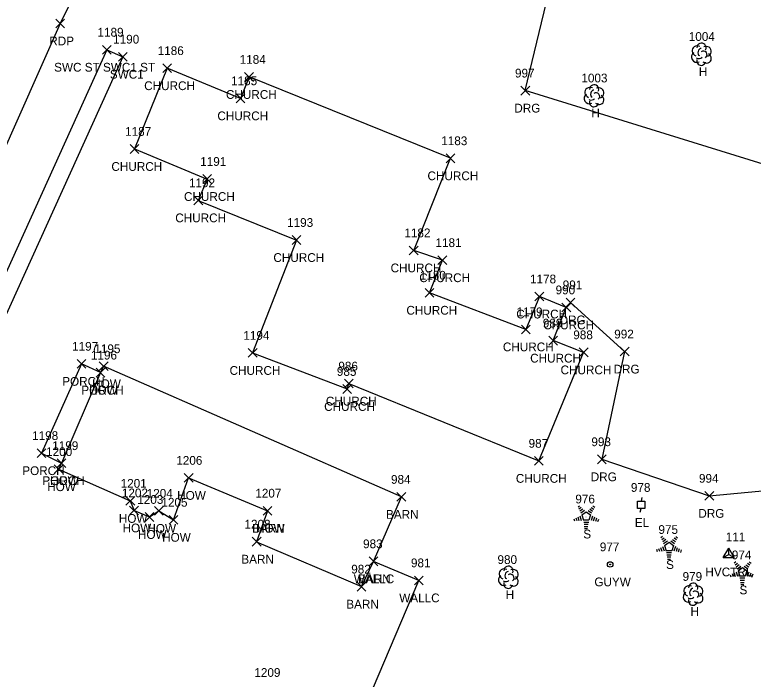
# Model space of a CAD drawing. Extents: x 1767353 to 1772625, y 740790 to 747702.
# Drawn here: x 1770077.3 to 1770245.8, y 742414.3 to 742566 of the extents above; entities that cross this region are included whole.
import ezdxf

# ---------------------------------------------------------------- set-up
doc = ezdxf.new("R2010")
doc.units = 0
for name, color, linetype in [('C_A', 7, 'Continuous'), ('C_I', 7, 'Continuous'), ('CPSM', 7, 'Continuous'), ('L_A', 7, 'Continuous'), ('L_I', 7, 'Continuous'), ('L_TIC', 7, 'Continuous'), ('LBC', 7, 'Continuous'), ('LBF', 7, 'Continuous'), ('LTC', 7, 'Continuous'), ('LTD', 7, 'Continuous'), ('LW', 7, 'Continuous'), ('P_A', 7, 'Continuous'), ('P_TIC', 7, 'Continuous'), ('PET', 7, 'Continuous'), ('R_A', 7, 'Continuous'), ('R_I', 7, 'Continuous'), ('R_TIC', 7, 'Continuous'), ('RDG', 7, 'Continuous'), ('RSW', 7, 'Continuous'), ('U_A', 7, 'Continuous'), ('U_I', 7, 'Continuous'), ('UEPT', 7, 'Continuous'), ('UPGW', 7, 'Continuous')]:
    doc.layers.add(name, color=color, linetype=linetype)

msp = doc.modelspace()

# ---------------------------------------------------------------- linework, layer by layer
at = {"layer": 'CPSM'}
for p, q in [((1770238.94, 742442.11), (1770240.19, 742444.27)), ((1770238.94, 742442.11), (1770240.19, 742442.83)), ((1770241.44, 742442.11), (1770240.19, 742444.27)), ((1770240.19, 742442.83), (1770240.19, 742444.27)), ((1770240.19, 742442.83), (1770240.19, 742442.83)), ((1770240.19, 742442.83), (1770241.44, 742442.11)), ((1770238.94, 742442.11), (1770241.44, 742442.11))]:
    msp.add_line(p, q, dxfattribs=at)
at = {"layer": 'L_TIC'}
for points in [[(1770111.12, 742552.84), (1770113.12, 742554.84)], [(1770113.12, 742552.84), (1770111.12, 742554.84)], [(1770129.77, 742550.84), (1770131.77, 742552.84)], [(1770131.77, 742550.84), (1770129.77, 742552.84)], [(1770127.81, 742545.96), (1770129.81, 742547.96)], [(1770129.81, 742545.96), (1770127.81, 742547.96)], [(1770103.64, 742534.4), (1770105.64, 742536.4)], [(1770105.64, 742534.4), (1770103.64, 742536.4)], [(1770175.74, 742532.27), (1770177.74, 742534.27)], [(1770177.74, 742532.27), (1770175.74, 742534.27)], [(1770120.2, 742527.54), (1770122.2, 742529.54)], [(1770122.2, 742527.54), (1770120.2, 742529.54)], [(1770118.21, 742522.67), (1770120.21, 742524.67)], [(1770120.21, 742522.67), (1770118.21, 742524.67)], [(1770140.59, 742513.61), (1770142.59, 742515.61)], [(1770142.59, 742513.61), (1770140.59, 742515.61)], [(1770167.33, 742511.24), (1770169.33, 742513.24)], [(1770169.33, 742511.24), (1770167.33, 742513.24)], [(1770173.87, 742509), (1770175.87, 742511)], [(1770175.87, 742509), (1770173.87, 742511)], [(1770170.93, 742501.57), (1770172.93, 742503.57)], [(1770172.93, 742501.57), (1770170.93, 742503.57)], [(1770196, 742500.71), (1770198, 742502.71)], [(1770198, 742500.71), (1770196, 742502.71)], [(1770202.15, 742498.22), (1770204.15, 742500.22)], [(1770204.15, 742498.22), (1770202.15, 742500.22)], [(1770192.94, 742493.21), (1770194.94, 742495.21)], [(1770194.94, 742493.21), (1770192.94, 742495.21)], [(1770199.16, 742490.64), (1770201.16, 742492.64)], [(1770201.16, 742490.64), (1770199.16, 742492.64)], [(1770206.1, 742487.96), (1770208.1, 742489.96)], [(1770208.1, 742487.96), (1770206.1, 742489.96)], [(1770130.6, 742487.83), (1770132.6, 742489.83)], [(1770132.6, 742487.83), (1770130.6, 742489.83)], [(1770091.54, 742485.34), (1770093.54, 742487.34)], [(1770093.54, 742485.34), (1770091.54, 742487.34)], [(1770096.61, 742484.79), (1770098.61, 742486.79)], [(1770098.61, 742484.79), (1770096.61, 742486.79)], [(1770095.89, 742483.33), (1770097.89, 742485.33)], [(1770097.89, 742483.33), (1770095.89, 742485.33)], [(1770095.89, 742483.33), (1770097.89, 742485.33)], [(1770097.89, 742483.33), (1770095.89, 742485.33)], [(1770152.17, 742479.6), (1770154.17, 742481.6)], [(1770154.17, 742479.6), (1770152.17, 742481.6)], [(1770152.56, 742480.83), (1770154.56, 742482.83)], [(1770154.56, 742480.83), (1770152.56, 742482.83)], [(1770082.43, 742464.95), (1770084.43, 742466.95)], [(1770084.43, 742464.95), (1770082.43, 742466.95)], [(1770195.9, 742463.19), (1770197.9, 742465.19)], [(1770197.9, 742463.19), (1770195.9, 742465.19)], [(1770086.35, 742461.29), (1770088.35, 742463.29)], [(1770088.35, 742461.29), (1770086.35, 742463.29)], [(1770087.02, 742462.66), (1770089.02, 742464.66)], [(1770089.02, 742462.66), (1770087.02, 742464.66)], [(1770087.02, 742462.66), (1770089.02, 742464.66)], [(1770089.02, 742462.66), (1770087.02, 742464.66)], [(1770116, 742459.3), (1770118, 742461.3)], [(1770118, 742459.3), (1770116, 742461.3)], [(1770164.52, 742454.96), (1770166.52, 742456.96)], [(1770166.52, 742454.96), (1770164.52, 742456.96)], [(1770102.69, 742454.05), (1770104.69, 742456.05)], [(1770104.69, 742454.05), (1770102.69, 742456.05)], [(1770103.54, 742451.87), (1770105.54, 742453.87)], [(1770105.54, 742451.87), (1770103.54, 742453.87)], [(1770109.21, 742451.77), (1770111.21, 742453.77)], [(1770111.21, 742451.77), (1770109.21, 742453.77)], [(1770133.98, 742451.81), (1770135.98, 742453.81)], [(1770135.98, 742451.81), (1770133.98, 742453.81)], [(1770133.98, 742451.81), (1770135.98, 742453.81)], [(1770135.98, 742451.81), (1770133.98, 742453.81)], [(1770107.05, 742450.38), (1770109.05, 742452.38)], [(1770109.05, 742450.38), (1770107.05, 742452.38)], [(1770112.57, 742449.73), (1770114.57, 742451.73)], [(1770114.57, 742449.73), (1770112.57, 742451.73)], [(1770131.51, 742444.74), (1770133.51, 742446.74)], [(1770133.51, 742444.74), (1770131.51, 742446.74)], [(1770158.15, 742440.25), (1770160.15, 742442.25)], [(1770160.15, 742440.25), (1770158.15, 742442.25)], [(1770158.15, 742440.25), (1770160.15, 742442.25)], [(1770160.15, 742440.25), (1770158.15, 742442.25)], [(1770168.51, 742435.9), (1770170.51, 742437.9)], [(1770170.51, 742435.9), (1770168.51, 742437.9)], [(1770155.45, 742434.47), (1770157.45, 742436.47)], [(1770157.45, 742434.47), (1770155.45, 742436.47)]]:
    msp.add_lwpolyline(points, dxfattribs=at)
at = {"layer": 'LBC'}
for points in [[(1770153.17, 742480.6), (1770153.56, 742481.83), (1770196.9, 742464.19), (1770207.1, 742488.96), (1770200.16, 742491.64), (1770203.15, 742499.22), (1770197, 742501.71), (1770193.94, 742494.21), (1770171.93, 742502.57), (1770174.87, 742510), (1770168.33, 742512.24), (1770176.74, 742533.27), (1770130.77, 742551.84), (1770128.81, 742546.96), (1770112.12, 742553.84), (1770104.64, 742535.4), (1770121.2, 742528.54), (1770119.21, 742523.67), (1770141.59, 742514.61), (1770131.6, 742488.83)], [(1770131.6, 742488.83), (1770153.17, 742480.6)], [(1770097.61, 742485.79), (1770096.89, 742484.33), (1770088.02, 742463.66), (1770087.35, 742462.29), (1770103.69, 742455.05), (1770104.54, 742452.87), (1770108.05, 742451.38), (1770110.21, 742452.77), (1770113.57, 742450.73), (1770117, 742460.3), (1770134.98, 742452.81)], [(1770165.52, 742455.96), (1770097.61, 742485.79)], [(1770156.45, 742435.47), (1770159.15, 742441.25), (1770165.52, 742455.96)], [(1770134.98, 742452.81), (1770132.51, 742445.74)], [(1770132.51, 742445.74), (1770156.45, 742435.47)]]:
    msp.add_lwpolyline(points, dxfattribs=at)
at = {"layer": 'LBF'}
msp.add_lwpolyline([(1770096.89, 742484.33), (1770092.54, 742486.34), (1770083.43, 742465.95), (1770088.02, 742463.66)], dxfattribs=at)
at = {"layer": 'LTC'}
for p, q in [((1770205.82, 742453.69), (1770206.18, 742453.95)), ((1770206.03, 742453.23), (1770206.56, 742453.61)), ((1770206.24, 742452.76), (1770206.95, 742453.27)), ((1770206.45, 742452.29), (1770207.33, 742452.93)), ((1770208.48, 742453.23), (1770209.16, 742452.74)), ((1770208.85, 742453.58), (1770209.4, 742453.18)), ((1770209.22, 742453.93), (1770209.64, 742453.63)), ((1770205.77, 742451.4), (1770206.04, 742450.57)), ((1770206.22, 742451.62), (1770206.55, 742450.6)), ((1770206.68, 742451.84), (1770207.69, 742452.57)), ((1770206.68, 742451.84), (1770207.07, 742450.65)), ((1770207.69, 742452.57), (1770208.69, 742451.85)), ((1770208.11, 742452.89), (1770208.92, 742452.3)), ((1770208.69, 742451.85), (1770208.3, 742450.65)), ((1770209.12, 742451.58), (1770208.79, 742450.54)), ((1770209.57, 742451.33), (1770209.28, 742450.44)), ((1770204.86, 742450.97), (1770205.01, 742450.5)), ((1770205.31, 742451.19), (1770205.52, 742450.54)), ((1770208.3, 742450.65), (1770207.07, 742450.65)), ((1770208.26, 742450.15), (1770207.11, 742450.15)), ((1770208.17, 742449.65), (1770207.19, 742449.65)), ((1770210.01, 742451.08), (1770209.78, 742450.35)), ((1770210.46, 742450.83), (1770210.27, 742450.25)), ((1770208.09, 742449.15), (1770207.26, 742449.15)), ((1770208.01, 742448.65), (1770207.33, 742448.65)), ((1770224.72, 742446.72), (1770225.07, 742446.98)), ((1770224.93, 742446.25), (1770225.46, 742446.64)), ((1770225.14, 742445.79), (1770225.84, 742446.3)), ((1770227.38, 742446.26), (1770228.05, 742445.77)), ((1770227.75, 742446.61), (1770228.3, 742446.21)), ((1770228.12, 742446.96), (1770228.54, 742446.65)), ((1770225.12, 742444.65), (1770225.45, 742443.63)), ((1770225.35, 742445.32), (1770226.23, 742445.96)), ((1770225.57, 742444.87), (1770226.58, 742445.6)), ((1770225.57, 742444.87), (1770225.96, 742443.67)), ((1770226.58, 742445.6), (1770227.58, 742444.88)), ((1770227, 742445.91), (1770227.81, 742445.33)), ((1770227.58, 742444.88), (1770227.19, 742443.67)), ((1770228.02, 742444.61), (1770227.68, 742443.57)), ((1770223.75, 742444), (1770223.9, 742443.53)), ((1770224.21, 742444.21), (1770224.42, 742443.56)), ((1770224.66, 742444.43), (1770224.93, 742443.6)), ((1770227.19, 742443.67), (1770225.96, 742443.67)), ((1770227.15, 742443.17), (1770226.01, 742443.17)), ((1770228.46, 742444.35), (1770228.18, 742443.47)), ((1770228.91, 742444.1), (1770228.67, 742443.38)), ((1770229.35, 742443.85), (1770229.17, 742443.28)), ((1770227.07, 742442.67), (1770226.08, 742442.67)), ((1770226.98, 742442.17), (1770226.15, 742442.17)), ((1770226.9, 742441.67), (1770226.23, 742441.67)), ((1770241.47, 742440.92), (1770241.82, 742441.18)), ((1770244.87, 742441.17), (1770245.29, 742440.86)), ((1770241.68, 742440.46), (1770242.21, 742440.84)), ((1770241.89, 742439.99), (1770242.59, 742440.5)), ((1770242.1, 742439.53), (1770242.98, 742440.17)), ((1770242.32, 742439.07), (1770243.33, 742439.81)), ((1770243.33, 742439.81), (1770244.33, 742439.08)), ((1770243.75, 742440.12), (1770244.56, 742439.53)), ((1770244.13, 742440.47), (1770244.8, 742439.97)), ((1770244.5, 742440.82), (1770245.05, 742440.42)), ((1770240.5, 742438.2), (1770240.65, 742437.74)), ((1770240.96, 742438.42), (1770241.17, 742437.77)), ((1770241.41, 742438.64), (1770241.68, 742437.8)), ((1770241.87, 742438.85), (1770242.2, 742437.83)), ((1770242.32, 742439.07), (1770242.71, 742437.88)), ((1770243.94, 742437.88), (1770242.71, 742437.88)), ((1770244.33, 742439.08), (1770243.94, 742437.88)), ((1770244.77, 742438.81), (1770244.43, 742437.77)), ((1770245.21, 742438.56), (1770244.93, 742437.68)), ((1770245.66, 742438.31), (1770245.42, 742437.58)), ((1770243.9, 742437.38), (1770242.76, 742437.38)), ((1770243.82, 742436.88), (1770242.83, 742436.88)), ((1770243.73, 742436.38), (1770242.9, 742436.38)), ((1770243.65, 742435.88), (1770242.98, 742435.88))]:
    msp.add_line(p, q, dxfattribs=at)
at = {"layer": 'LTD'}
for p, q in [((1770233.93, 742557.07), (1770233.93, 742557.07)), ((1770233.93, 742557.07), (1770233.93, 742557.07)), ((1770209.44, 742547.6), (1770209.44, 742547.6)), ((1770209.44, 742547.6), (1770209.44, 742547.6)), ((1770189.9, 742437.65), (1770189.9, 742437.65)), ((1770189.9, 742437.65), (1770189.9, 742437.65)), ((1770232.04, 742433.8), (1770232.04, 742433.8)), ((1770232.04, 742433.8), (1770232.04, 742433.8))]:
    msp.add_line(p, q, dxfattribs=at)
for centre in [(1770233.98, 742558.5), (1770209.49, 742549.03), (1770189.95, 742439.09), (1770232.09, 742435.24)]:
    msp.add_arc(centre, 1.05, 335.5272, 180.9563, dxfattribs=at)
for centre, major_axis, ratio, start_param, end_param in [((1770233.14, 742557.73), (1.21, -0.51), 0.895232, 1.570796, 4.712389), ((1770232.85, 742556.36), (0.58, -1.04), 0.959034, 3.141593, 6.283185), ((1770233.72, 742557.53), (-0.208, -0.792), 0.645439, 3.141593, 6.283185), ((1770234.43, 742556.9), (-0.5, 0.667), 0.989748, 3.141593, 6.283185), ((1770234.97, 742557.65), (-1.14, -0.48), 0.949671, 1.570796, 4.712389), ((1770233.93, 742555.57), (0.26, 1.06), 0.942809, 1.570796, 4.712389), ((1770233.48, 742556.32), (-0.625, -0.083), 0.423636, 0, 3.141593), ((1770234.93, 742556.23), (-1.09, 0.79), 0.841452, 1.570796, 4.712389), ((1770208.65, 742548.26), (1.21, -0.51), 0.895232, 1.570796, 4.712389), ((1770209.23, 742548.05), (-0.208, -0.792), 0.645439, 3.141593, 6.283185), ((1770210.48, 742548.18), (-1.14, -0.48), 0.949671, 1.570796, 4.712389), ((1770208.36, 742546.89), (0.58, -1.04), 0.959034, 3.141593, 6.283185), ((1770209.94, 742547.43), (-0.5, 0.667), 0.989748, 3.141593, 6.283185), ((1770210.44, 742546.76), (-1.09, 0.79), 0.841452, 1.570796, 4.712389), ((1770209.44, 742546.1), (0.26, 1.06), 0.942809, 1.570796, 4.712389), ((1770208.98, 742546.85), (-0.625, -0.083), 0.423636, 0, 3.141593), ((1770189.11, 742438.32), (1.21, -0.51), 0.895232, 1.570796, 4.712389), ((1770190.94, 742438.24), (-1.14, -0.48), 0.949671, 1.570796, 4.712389), ((1770188.82, 742436.94), (0.58, -1.04), 0.959034, 3.141593, 6.283185), ((1770189.69, 742438.11), (-0.208, -0.792), 0.645439, 3.141593, 6.283185), ((1770190.4, 742437.49), (-0.5, 0.667), 0.989748, 3.141593, 6.283185), ((1770189.9, 742436.15), (0.26, 1.06), 0.942809, 1.570796, 4.712389), ((1770189.44, 742436.9), (-0.625, -0.083), 0.423636, 0, 3.141593), ((1770190.9, 742436.82), (-1.09, 0.79), 0.841452, 1.570796, 4.712389), ((1770231.25, 742434.47), (1.21, -0.51), 0.895232, 1.570796, 4.712389), ((1770231.83, 742434.26), (-0.208, -0.792), 0.645439, 3.141593, 6.283185), ((1770232.54, 742433.64), (-0.5, 0.667), 0.989748, 3.141593, 6.283185), ((1770233.08, 742434.39), (-1.14, -0.48), 0.949671, 1.570796, 4.712389), ((1770230.96, 742433.1), (0.58, -1.04), 0.959034, 3.141593, 6.283185), ((1770231.58, 742433.05), (-0.625, -0.083), 0.423636, 0, 3.141593), ((1770233.04, 742432.97), (-1.09, 0.79), 0.841452, 1.570796, 4.712389), ((1770232.04, 742432.3), (0.26, 1.06), 0.942809, 1.570796, 4.712389)]:
    msp.add_ellipse(centre, major_axis=major_axis, ratio=ratio, start_param=start_param, end_param=end_param, dxfattribs=at)
at = {"layer": 'LW'}
msp.add_lwpolyline([(1770155.04, 742402.89), (1770169.51, 742436.9), (1770159.15, 742441.25)], dxfattribs=at)
at = {"layer": 'P_TIC'}
for points in [[(1770086.72, 742563.06), (1770088.72, 742565.06)], [(1770088.72, 742563.06), (1770086.72, 742565.06)]]:
    msp.add_lwpolyline(points, dxfattribs=at)
at = {"layer": 'PET'}
msp.add_lwpolyline([(1770147.48, 742699.94), (1770126.77, 742647.43), (1770093.35, 742575.6), (1770087.72, 742564.06), (1770014.02, 742398.02), (1769942.32, 742243.2), (1769914.15, 742124.85), (1769908.32, 742119.68), (1769902.88, 742101.36), (1769903.35, 742099.19), (1769904.66, 742097.46), (1769909.68, 742095.79), (1770083.39, 742045.68), (1770106.4, 742043.42), (1770086.96, 742009.25), (1770086.23, 742007.27), (1770086.55, 742005.47), (1770087.9, 742003.62), (1770089.26, 742002.56), (1770097.29, 741998.16), (1770140.08, 741981.73)], dxfattribs=at)
at = {"layer": 'R_TIC'}
for points in [[(1770097.34, 742557.06), (1770099.34, 742559.06)], [(1770099.34, 742557.06), (1770097.34, 742559.06)], [(1770097.34, 742557.06), (1770099.34, 742559.06)], [(1770099.34, 742557.06), (1770097.34, 742559.06)], [(1770100.99, 742555.46), (1770102.99, 742557.46)], [(1770102.99, 742555.46), (1770100.99, 742557.46)], [(1770192.8, 742547.72), (1770194.8, 742549.72)], [(1770194.8, 742547.72), (1770192.8, 742549.72)], [(1770203.13, 742499.37), (1770205.13, 742501.37)], [(1770205.13, 742499.37), (1770203.13, 742501.37)], [(1770215.45, 742488.14), (1770217.45, 742490.14)], [(1770217.45, 742488.14), (1770215.45, 742490.14)], [(1770210.23, 742463.55), (1770212.23, 742465.55)], [(1770212.23, 742463.55), (1770210.23, 742465.55)], [(1770234.77, 742455.2), (1770236.77, 742457.2)], [(1770236.77, 742455.2), (1770234.77, 742457.2)]]:
    msp.add_lwpolyline(points, dxfattribs=at)
at = {"layer": 'RDG'}
msp.add_lwpolyline([(1770204.13, 742500.37), (1770216.45, 742489.14), (1770211.23, 742464.55), (1770235.77, 742456.2), (1770257.57, 742458.3), (1770267.19, 742526.02), (1770193.8, 742548.72), (1770201.83, 742582.22)], dxfattribs=at)
at = {"layer": 'RSW'}
for points in [[(1770098.34, 742558.06), (1770024.1, 742393.92), (1769953.58, 742237.06), (1769937.36, 742200.11), (1769932.58, 742188.49)], [(1770098.34, 742558.06), (1770101.99, 742556.46), (1770027.61, 742392.19), (1769957.88, 742235.71), (1769937.16, 742186.55), (1769936.48, 742178.62)]]:
    msp.add_lwpolyline(points, dxfattribs=at)
at = {"layer": 'UEPT'}
for p, q in [((1770219.41, 742453.29), (1770219.41, 742454.96)), ((1770219.41, 742454.96), (1770221.07, 742454.96)), ((1770220.41, 742455.79), (1770220.24, 742454.96)), ((1770221.07, 742454.96), (1770221.07, 742453.29)), ((1770221.07, 742453.29), (1770219.41, 742453.29)), ((1770219.99, 742452.46), (1770220.24, 742453.29)), ((1770220.24, 742454.12), (1770220.24, 742454.12))]:
    msp.add_line(p, q, dxfattribs=at)
at = {"layer": 'UPGW'}
for radius in [0.625, 0.0833]:
    msp.add_circle((1770213.15, 742440.55), radius, dxfattribs=at)

# ---------------------------------------------------------------- texts
at = {"layer": 'C_A'}
msp.add_text('HVCTRL', height=2, dxfattribs=at).set_placement((1770234.88, 742437.83))
at = {"layer": 'C_I'}
msp.add_text('111', height=2, dxfattribs=at).set_placement((1770239.52, 742445.83))
at = {"layer": 'L_A'}
for s, p in [('H', (1770233.37, 742552.07)), ('CHURCH', (1770106.86, 742548.84)), ('CHURCH', (1770125.51, 742546.84)), ('CHURCH', (1770123.55, 742541.96)), ('H', (1770208.87, 742542.6)), ('CHURCH', (1770099.38, 742530.4)), ('CHURCH', (1770171.48, 742528.27)), ('CHURCH', (1770115.94, 742523.54)), ('CHURCH', (1770113.95, 742518.67)), ('CHURCH', (1770136.33, 742509.61)), ('CHURCH', (1770163.07, 742507.24)), ('CHURCH', (1770169.61, 742505)), ('CHURCH', (1770166.67, 742497.57)), ('CHURCH', (1770191.74, 742496.71)), ('CHURCH', (1770197.89, 742494.22)), ('CHURCH', (1770188.68, 742489.21)), ('CHURCH', (1770194.9, 742486.64)), ('CHURCH', (1770126.34, 742483.83)), ('CHURCH', (1770201.84, 742483.96)), ('PORCH', (1770088.16, 742481.34)), ('HOW', (1770095, 742480.79)), ('PORCH', (1770092.52, 742479.33)), ('HOW', (1770094.28, 742479.33)), ('CHURCH', (1770148.3, 742476.83)), ('CHURCH', (1770147.91, 742475.6)), ('PORCH', (1770079.05, 742460.95)), ('PORCH', (1770083.64, 742458.66)), ('HOW', (1770085.4, 742458.66)), ('CHURCH', (1770191.64, 742459.19)), ('HOW', (1770084.74, 742457.29)), ('HOW', (1770114.39, 742455.3)), ('BARN', (1770162.03, 742450.96)), ('HOW', (1770101.08, 742450.05)), ('HOW', (1770101.93, 742447.87)), ('HOW', (1770107.59, 742447.77)), ('BARN', (1770131.49, 742447.81)), ('HOW', (1770132.37, 742447.81)), ('HOW', (1770105.44, 742446.38)), ('S', (1770207.02, 742446.48)), ('HOW', (1770110.95, 742445.73)), ('BARN', (1770129.02, 742440.74)), ('S', (1770225.91, 742439.51)), ('WALLC', (1770154.68, 742436.25)), ('BARN', (1770155.66, 742436.25)), ('H', (1770189.33, 742432.65)), ('S', (1770242.66, 742433.72)), ('WALLC', (1770165.04, 742431.9)), ('BARN', (1770152.96, 742430.47)), ('H', (1770231.47, 742428.8))]:
    msp.add_text(s, height=2, dxfattribs=at).set_placement(p)
at = {"layer": 'L_I'}
for s, p in [('1004', (1770231.08, 742560.07)), ('1186', (1770109.94, 742556.84)), ('1184', (1770128.64, 742554.84)), ('1003', (1770206.59, 742550.6)), ('1185', (1770126.68, 742549.96)), ('1187', (1770102.51, 742538.4)), ('1183', (1770174.62, 742536.27)), ('1191', (1770119.64, 742531.54)), ('1192', (1770117.08, 742526.67)), ('1193', (1770139.46, 742517.61)), ('1182', (1770166.21, 742515.24)), ('1181', (1770173.31, 742513)), ('1180', (1770169.72, 742505.57)), ('1178', (1770194.87, 742504.71)), ('990', (1770200.7, 742502.22)), ('1179', (1770191.8, 742497.21)), ('989', (1770197.79, 742494.64)), ('1194', (1770129.48, 742491.83)), ('988', (1770204.74, 742491.96)), ('1197', (1770090.41, 742489.34)), ('1195', (1770095.49, 742488.79)), ('1196', (1770094.71, 742487.33)), ('1196', (1770094.71, 742487.33)), ('986', (1770151.15, 742484.83)), ('985', (1770150.81, 742483.6)), ('1198', (1770081.3, 742468.95)), ('1199', (1770085.88, 742466.66)), ('1199', (1770085.88, 742466.66)), ('987', (1770194.54, 742467.19)), ('1200', (1770084.49, 742465.29)), ('1206', (1770114.18, 742463.3)), ('1201', (1770101.49, 742458.05)), ('984', (1770163.16, 742458.96)), ('1202', (1770101.77, 742455.87)), ('1203', (1770105.28, 742454.38)), ('1204', (1770107.43, 742455.77)), ('1207', (1770132.21, 742455.81)), ('1207', (1770132.21, 742455.81)), ('976', (1770205.21, 742454.48)), ('1205', (1770110.79, 742453.73)), ('1208', (1770129.74, 742448.74)), ('975', (1770224.16, 742447.51)), ('983', (1770156.79, 742444.25)), ('983', (1770156.79, 742444.25)), ('974', (1770240.91, 742441.72)), ('981', (1770167.71, 742439.9)), ('980', (1770187.45, 742440.65)), ('982', (1770154.09, 742438.47)), ('979', (1770229.67, 742436.8)), ('1209', (1770131.99, 742414.87))]:
    msp.add_text(s, height=2, dxfattribs=at).set_placement(p)
at = {"layer": 'LTC'}
for p in [(1770207.57, 742451.59), (1770226.47, 742444.61), (1770243.22, 742438.82)]:
    msp.add_text('.', height=1.04, rotation=270, dxfattribs=at).set_placement(p)
at = {"layer": 'P_A'}
msp.add_text('RDP', height=2, dxfattribs=at).set_placement((1770085.21, 742559.06))
at = {"layer": 'R_A'}
for s, p in [('SWC ST SWC1 ST', (1770086.32, 742553.06)), ('SWC ST SWC1 ST', (1770086.32, 742553.06)), ('SWC1', (1770099.03, 742551.46)), ('DRG', (1770191.29, 742543.72)), ('DRG', (1770201.62, 742495.37)), ('DRG', (1770213.93, 742484.14)), ('DRG', (1770208.72, 742459.55)), ('DRG', (1770233.26, 742451.2))]:
    msp.add_text(s, height=2, dxfattribs=at).set_placement(p)
at = {"layer": 'R_I'}
for s, p in [('1189', (1770096.21, 742561.06)), ('1189', (1770096.21, 742561.06)), ('1190', (1770099.78, 742559.46)), ('997', (1770191.44, 742551.72)), ('991', (1770202.33, 742503.37)), ('992', (1770214.08, 742492.14)), ('993', (1770208.87, 742467.55)), ('994', (1770233.41, 742459.2))]:
    msp.add_text(s, height=2, dxfattribs=at).set_placement(p)
at = {"layer": 'U_A'}
for s, p in [('EL', (1770218.78, 742449.12)), ('GUYW', (1770209.55, 742435.55))]:
    msp.add_text(s, height=2, dxfattribs=at).set_placement(p)
at = {"layer": 'U_I'}
for s, p in [('978', (1770217.88, 742457.12)), ('977', (1770210.79, 742443.55))]:
    msp.add_text(s, height=2, dxfattribs=at).set_placement(p)

doc.saveas('drawing.dxf')
